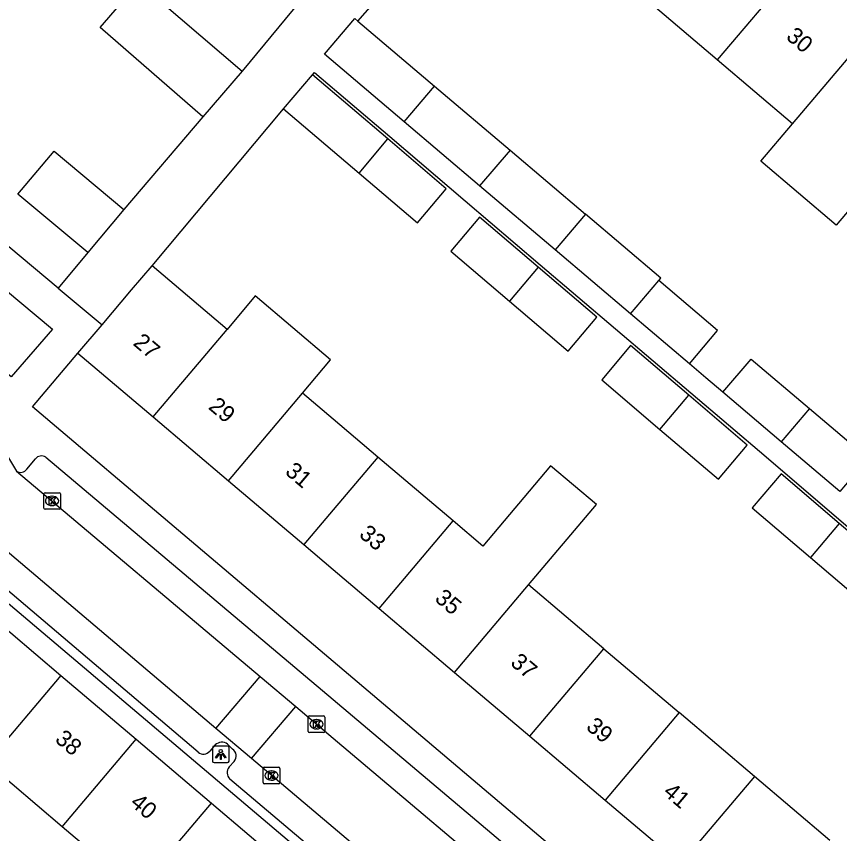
# Model space of a CAD drawing. Extents: x 162532 to 163264, y 381233 to 382042.
# Drawn here: x 162980.9 to 163030.56, y 381569.4 to 381618.69 of the extents above; entities that cross this region are included whole.
import ezdxf

# ---------------------------------------------------------------- set-up
doc = ezdxf.new("R2010")
doc.units = 0
for name, color, linetype in [('IMGEO_Kolk', 7, 'Continuous'), ('IMGEO_Lichtpunt', 7, 'Continuous'), ('IMGEO_Muur', 7, 'Continuous'), ('IMGEO_Pand', 7, 'Continuous'), ('IMGEO_Pand_nummerreeks', 7, 'Continuous'), ('IMGEO_Rijbaan_lokaal_open', 7, 'Continuous'), ('IMGEO_Voetpad_open', 7, 'Continuous')]:
    doc.layers.add(name, color=color, linetype=linetype)

msp = doc.modelspace()

# ---------------------------------------------------------------- linework, layer by layer
at = {"layer": 'IMGEO_Kolk'}
for p, q in [((162982.548, 381589.032), (162982.548, 381589.884)), ((162982.623, 381589.958), (162983.475, 381589.958)), ((162983.549, 381589.884), (162983.549, 381589.032)), ((162983.036, 381589.738), (162983.061, 381589.738)), ((162983.475, 381588.958), (162982.623, 381588.958)), ((162983.059, 381589.178), (162983.034, 381589.178)), ((162998.579, 381576.486), (162999.431, 381576.486)), ((162998.504, 381575.56), (162998.504, 381576.412)), ((162998.992, 381576.266), (162999.017, 381576.266)), ((162999.505, 381576.412), (162999.505, 381575.56)), ((162999.431, 381575.486), (162998.579, 381575.486)), ((162999.015, 381575.706), (162998.99, 381575.706)), ((162995.786, 381572.469), (162995.786, 381573.321)), ((162995.861, 381573.395), (162996.713, 381573.395)), ((162996.274, 381573.175), (162996.299, 381573.175)), ((162996.787, 381573.321), (162996.787, 381572.469)), ((162996.297, 381572.615), (162996.272, 381572.615)), ((162996.713, 381572.395), (162995.861, 381572.395))]:
    msp.add_line(p, q, dxfattribs=at)
for points in [[(162982.548, 381589.032), (162982.548, 381589.884)], [(162982.623, 381589.958), (162983.475, 381589.958)], [(162983.549, 381589.884), (162983.549, 381589.032)], [(162982.869, 381589.658), (162982.992, 381589.658), (162982.992, 381589.507), (162983.122, 381589.658), (162983.286, 381589.658), (162983.14, 381589.507), (162983.293, 381589.258), (162983.141, 381589.258), (162983.056, 381589.422), (162982.992, 381589.355), (162982.992, 381589.258), (162982.869, 381589.258), (162982.869, 381589.658)], [(162983.475, 381588.958), (162982.623, 381588.958)], [(162998.579, 381576.486), (162999.431, 381576.486)], [(162998.504, 381575.56), (162998.504, 381576.412)], [(162998.825, 381576.186), (162998.948, 381576.186), (162998.948, 381576.035), (162999.078, 381576.186), (162999.242, 381576.186), (162999.096, 381576.035), (162999.249, 381575.786), (162999.097, 381575.786), (162999.012, 381575.95), (162998.948, 381575.883), (162998.948, 381575.786), (162998.825, 381575.786), (162998.825, 381576.186)], [(162999.505, 381576.412), (162999.505, 381575.56)], [(162999.431, 381575.486), (162998.579, 381575.486)], [(162995.786, 381572.469), (162995.786, 381573.321)], [(162995.861, 381573.395), (162996.713, 381573.395)], [(162996.107, 381573.095), (162996.23, 381573.095), (162996.23, 381572.944), (162996.36, 381573.095), (162996.524, 381573.095), (162996.378, 381572.944), (162996.531, 381572.695), (162996.379, 381572.695), (162996.294, 381572.859), (162996.23, 381572.792), (162996.23, 381572.695), (162996.107, 381572.695), (162996.107, 381573.095)], [(162996.787, 381573.321), (162996.787, 381572.469)], [(162996.713, 381572.395), (162995.861, 381572.395)]]:
    msp.add_lwpolyline(points, dxfattribs=at)
for centre, start, end in [((162982.625, 381589.882), 91.552, 178.448), ((162982.625, 381589.882), 91.552, 178.448), ((162983.473, 381589.882), 1.552, 88.448), ((162983.473, 381589.882), 1.552, 88.448), ((162982.625, 381589.034), 181.552, 268.448), ((162982.625, 381589.034), 181.552, 268.448), ((162983.473, 381589.034), 271.552, 358.448), ((162983.473, 381589.034), 271.552, 358.448), ((162998.581, 381576.41), 91.552, 178.448), ((162998.581, 381576.41), 91.552, 178.448), ((162999.429, 381576.41), 1.552, 88.448), ((162999.429, 381576.41), 1.552, 88.448), ((162998.581, 381575.562), 181.552, 268.448), ((162998.581, 381575.562), 181.552, 268.448), ((162999.429, 381575.562), 271.552, 358.448), ((162999.429, 381575.562), 271.552, 358.448), ((162995.863, 381573.319), 91.552, 178.448), ((162995.863, 381573.319), 91.552, 178.448), ((162996.711, 381573.319), 1.552, 88.448), ((162996.711, 381573.319), 1.552, 88.448), ((162995.863, 381572.471), 181.552, 268.448), ((162995.863, 381572.471), 181.552, 268.448), ((162996.711, 381572.471), 271.552, 358.448), ((162996.711, 381572.471), 271.552, 358.448)]:
    msp.add_arc(centre, 0.0765, start, end, dxfattribs=at)
for centre, major_axis, ratio, start_param, end_param in [((162983.035, 381589.458), (-0.387, 0.002), 0.722429, 4.712389, 7.853982), ((162983.06, 381589.458), (-0.39, 0.002), 0.717154, 1.570796, 4.712389), ((162998.991, 381575.986), (-0.387, 0.002), 0.722429, 4.712389, 7.853982), ((162999.016, 381575.986), (-0.39, 0.002), 0.717154, 1.570796, 4.712389), ((162996.273, 381572.895), (-0.387, 0.002), 0.722429, 4.712389, 7.853982), ((162996.298, 381572.895), (-0.39, 0.002), 0.717154, 1.570796, 4.712389)]:
    msp.add_ellipse(centre, major_axis=major_axis, ratio=ratio, start_param=start_param, end_param=end_param, dxfattribs=at)
at = {"layer": 'IMGEO_Lichtpunt'}
for p, q in [((162992.731, 381574.575), (162992.731, 381573.768)), ((162992.731, 381574.575), (162992.731, 381573.768)), ((162993.633, 381574.67), (162992.825, 381574.67)), ((162993.633, 381574.67), (162992.825, 381574.67)), ((162993.727, 381573.768), (162993.727, 381574.575)), ((162993.727, 381573.768), (162993.727, 381574.575)), ((162992.825, 381573.674), (162993.633, 381573.674)), ((162992.825, 381573.674), (162993.633, 381573.674))]:
    msp.add_line(p, q, dxfattribs=at)
for points in [[(162993.105, 381574.239), (162993.144, 381574.211), (162992.956, 381573.949), (162992.918, 381573.976), (162993.105, 381574.239)], [(162993.207, 381574.191), (162993.254, 381574.191), (162993.254, 381573.869), (162993.207, 381573.869), (162993.207, 381574.191)], [(162993.317, 381574.211), (162993.355, 381574.238), (162993.542, 381573.976), (162993.503, 381573.948), (162993.317, 381574.211)]]:
    msp.add_lwpolyline(points, dxfattribs=at)
msp.add_circle((162993.23, 381574.373), 0.0994, dxfattribs=at)
for centre, start, end in [((162992.825, 381574.575), 90, 180), ((162992.825, 381574.575), 90, 180), ((162993.633, 381574.575), 0, 90), ((162993.633, 381574.575), 0, 90), ((162992.825, 381573.768), 180, 270), ((162992.825, 381573.768), 180, 270), ((162993.633, 381573.768), 270, 0), ((162993.633, 381573.768), 270, 360)]:
    msp.add_arc(centre, 0.0946, start, end, dxfattribs=at)
at = {"layer": 'IMGEO_Muur'}
msp.add_lwpolyline([(162983.414, 381602.297), (162971.989, 381611.847)], dxfattribs=at)
at = {"layer": 'IMGEO_Pand'}
for points in [[(163027.674, 381621.349), (163023.184, 381616.074)], [(162992.138, 381612.621), (162985.957, 381618.029), (162988.275, 381620.732), (162994.51, 381615.388)], [(163023.184, 381616.074), (163018.644, 381619.935)], [(163004.295, 381612.326), (162999.485, 381616.407), (163001.318, 381618.567), (163001.502, 381618.411)], [(163001.502, 381618.411), (163006.131, 381614.483)], [(163027.724, 381612.212), (163032.213, 381617.487)], [(163027.724, 381612.212), (163023.184, 381616.074)], [(162994.51, 381615.388), (162992.138, 381612.621)], [(162997.018, 381613.111), (162998.764, 381615.162)], [(163003.308, 381611.294), (162998.764, 381615.162)], [(163004.295, 381612.326), (163006.131, 381614.483)], [(163006.131, 381614.483), (163010.681, 381610.623)], [(162997.018, 381613.111), (163001.568, 381609.238)], [(163008.845, 381608.466), (163004.295, 381612.326)], [(163032.264, 381608.351), (163030.35, 381606.102), (163025.811, 381609.964), (163027.724, 381612.212)], [(163001.568, 381609.238), (163003.308, 381611.294)], [(163001.568, 381609.238), (163005.093, 381606.237), (163006.833, 381608.292), (163003.308, 381611.294)], [(162985.204, 381604.439), (162980.992, 381607.96), (162983.166, 381610.561), (162987.378, 381607.04)], [(163010.681, 381610.623), (163008.845, 381608.466)], [(163010.681, 381610.623), (163015.231, 381606.763)], [(163013.395, 381604.606), (163008.845, 381608.466)], [(162987.378, 381607.04), (162985.204, 381604.439)], [(163015.231, 381606.763), (163013.395, 381604.606)], [(163019.653, 381602.753), (163019.781, 381602.904), (163015.231, 381606.763)], [(163012.388, 381603.564), (163008.841, 381606.583), (163007.101, 381604.527), (163010.648, 381601.508)], [(163017.945, 381600.747), (163013.395, 381604.606)], [(162986.061, 381600.085), (162987.845, 381602.189), (162989.08, 381603.646)], [(162993.605, 381599.811), (162989.08, 381603.646)], [(163012.388, 381603.564), (163010.648, 381601.508)], [(163010.648, 381601.508), (163014.182, 381598.499), (163015.922, 381600.555), (163012.388, 381603.564)], [(163017.945, 381600.747), (163019.653, 381602.753)], [(163021.501, 381597.729), (163023.209, 381599.736), (163019.653, 381602.753)], [(162998.152, 381595.958), (162999.858, 381597.974), (162995.309, 381601.824), (162993.605, 381599.811)], [(163021.501, 381597.729), (163017.945, 381600.747)], [(162984.611, 381598.375), (162986.061, 381600.085)], [(162989.14, 381594.536), (162993.605, 381599.811)], [(163021.468, 381595.833), (163017.949, 381598.829), (163016.21, 381596.773), (163019.729, 381593.778)], [(162984.611, 381598.375), (162989.14, 381594.536)], [(163023.524, 381596.013), (163025.232, 381598.02), (163028.752, 381595.033)], [(162993.686, 381590.682), (162998.152, 381595.958)], [(163002.698, 381592.105), (163000, 381594.392), (162998.152, 381595.958)], [(163019.729, 381593.778), (163021.468, 381595.833)], [(163019.729, 381593.778), (163023.259, 381590.773), (163024.998, 381592.828), (163021.468, 381595.833)], [(163027.045, 381593.027), (163023.524, 381596.013)], [(163028.752, 381595.033), (163027.045, 381593.027)], [(163028.752, 381595.033), (163032.284, 381592.036), (163030.577, 381590.031)], [(162989.14, 381594.536), (162993.686, 381590.682)], [(163030.577, 381590.031), (163027.045, 381593.027)], [(163002.698, 381592.105), (163000, 381588.917), (162998.232, 381586.828)], [(163007.245, 381588.252), (163002.698, 381592.105)], [(163011.792, 381584.398), (163015.89, 381589.24), (163013.13, 381591.575), (163009.034, 381586.735), (163007.245, 381588.252)], [(163030.548, 381588.103), (163027.036, 381591.093), (163025.296, 381589.039), (163028.809, 381586.048)], [(162993.686, 381590.682), (162998.232, 381586.828)], [(163002.778, 381582.975), (163007.245, 381588.252)], [(163030.548, 381588.103), (163028.809, 381586.048)], [(163028.809, 381586.048), (163032.353, 381583.031), (163034.092, 381585.086), (163030.548, 381588.103)], [(162998.232, 381586.828), (163000, 381585.33), (163002.778, 381582.975)], [(163007.325, 381579.12), (163011.792, 381584.398)], [(163016.339, 381580.545), (163011.792, 381584.398)], [(163002.778, 381582.975), (163007.325, 381579.12)], [(162979.027, 381582.788), (162983.573, 381578.934)], [(163011.871, 381575.266), (163016.339, 381580.545)], [(163016.339, 381580.545), (163020.886, 381576.691)], [(162983.573, 381578.934), (162979.105, 381573.662)], [(162983.573, 381578.934), (162988.119, 381575.079)], [(163007.325, 381579.12), (163011.871, 381575.266)], [(163020.886, 381576.691), (163016.417, 381571.413)], [(163025.433, 381572.838), (163020.886, 381576.691)], [(162983.65, 381569.806), (162988.119, 381575.079)], [(162988.119, 381575.079), (162992.665, 381571.225)], [(163011.871, 381575.266), (163016.417, 381571.413)], [(162983.65, 381569.806), (162979.105, 381573.662)], [(163025.433, 381572.838), (163020.964, 381567.558)], [(163029.979, 381568.985), (163025.433, 381572.838)], [(162988.196, 381565.951), (162992.665, 381571.225)], [(162992.665, 381571.225), (162997.211, 381567.37)], [(163016.417, 381571.413), (163020.964, 381567.558)], [(162988.196, 381565.951), (162983.65, 381569.806)]]:
    msp.add_lwpolyline(points, dxfattribs=at)
at = {"layer": 'IMGEO_Rijbaan_lokaal_open'}
for points in [[(162978.815, 381594.719), (162980.91, 381591.262)], [(162980.91, 381591.262), (162995.604, 381578.864)], [(162992.932, 381575.733), (162978.6, 381587.852)], [(162992.932, 381575.733), (162995.604, 381578.864)], [(162995.604, 381578.864), (162997.752, 381577.051)], [(162995.077, 381573.919), (162997.752, 381577.051)], [(162997.752, 381577.051), (163000, 381575.154), (163012.294, 381564.78), (163028.675, 381550.968)], [(162995.077, 381573.919), (162992.932, 381575.733)], [(163025.989, 381547.783), (163000, 381569.757), (162995.077, 381573.919)]]:
    msp.add_lwpolyline(points, dxfattribs=at)
at = {"layer": 'IMGEO_Voetpad_open'}
for points in [[(163001.502, 381618.411), (163009.603, 381627.625)], [(162999.317, 381621.207), (162994.51, 381615.388)], [(162964.065, 381615.701), (162983.082, 381599.812), (162980.589, 381596.946), (162961.61, 381612.777)], [(162998.764, 381615.162), (162998.887, 381615.303), (163003.429, 381611.437), (163007.969, 381607.572), (163012.509, 381603.707), (163017.049, 381599.842), (163021.59, 381595.977), (163026.13, 381592.111), (163030.67, 381588.247), (163035.21, 381584.382), (163039.751, 381580.517), (163044.291, 381576.652), (163048.831, 381572.787), (163053.502, 381568.81), (163053.379, 381568.666)], [(162989.08, 381603.646), (162997.018, 381613.111)], [(162992.138, 381612.621), (162987.378, 381607.04)], [(162983.414, 381602.297), (162971.989, 381611.847)], [(162985.204, 381604.439), (162983.414, 381602.297)], [(162983.414, 381602.297), (162986.061, 381600.085)], [(163039.317, 381552), (163036.569, 381548.778), (163000, 381579.765), (162981.863, 381595.134), (162984.611, 381598.375)], [(163023.524, 381596.013), (163022.495, 381596.886), (163021.501, 381597.729)], [(162981.53, 381591.38), (162982.043, 381592.001)], [(162982.673, 381592.097), (163000, 381577.483), (163013.472, 381566.121)], [(163029.277, 381540.181), (163030.105, 381541.182), (162975.401, 381587.503), (162974.802, 381586.815), (162974.491, 381587.076)], [(162991.861, 381574.305), (162978.081, 381585.992)], [(162992.894, 381574.742), (162992.566, 381574.363)], [(162993.933, 381574.484), (162993.63, 381574.785)], [(162993.731, 381573.412), (162994.041, 381573.751)], [(163024.89, 381546.313), (163000, 381567.408), (162993.773, 381572.685)]]:
    msp.add_lwpolyline(points, dxfattribs=at)
for centre, radius, start, end in [((162982.411, 381591.699), 0.476, 56.6585, 140.6698), ((162981.165, 381591.609), 0.431, 233.6936, 327.858), ((162993.287, 381574.34), 0.562, 52.3686, 134.3186), ((162993.685, 381574.073), 0.48, 317.8436, 58.9197), ((162992.184, 381574.694), 0.505, 230.2699, 319.1363), ((162994.158, 381573.072), 0.546, 141.4459, 225.1669)]:
    msp.add_arc(centre, radius, start, end, dxfattribs=at)

# ---------------------------------------------------------------- texts
at = {"layer": 'IMGEO_Pand_nummerreeks'}
for s, rotation, p in [('30', 319.6097, (163027.279, 381617.377)), ('27', 319.7116, (162987.881, 381598.907)), ('29', 319.7116, (162992.423, 381595.057)), ('31', 319.7116, (162997.051, 381591.134)), ('33', 319.7116, (163001.514, 381587.351)), ('35', 319.7116, (163006.079, 381583.481)), ('37', 319.7116, (163010.644, 381579.611)), ('39', 319.7116, (163015.209, 381575.741)), ('38', 319.7348, (162983.166, 381574.988)), ('41', 319.7116, (163019.86, 381571.798)), ('40', 319.7348, (162987.7, 381571.148))]:
    msp.add_text(s, height=1, rotation=rotation, dxfattribs=at).set_placement(p)

doc.saveas('drawing.dxf')
